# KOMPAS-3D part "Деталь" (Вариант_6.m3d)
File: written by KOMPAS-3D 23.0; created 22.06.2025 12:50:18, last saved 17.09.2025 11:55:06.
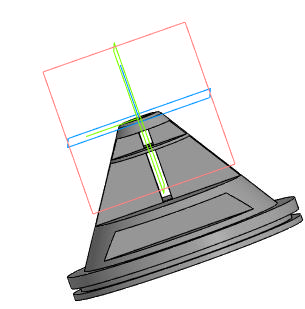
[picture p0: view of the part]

Document properties: Автор: admin; Организация: MGTU; Полное имя файла: C:\Users\ssafo\OneDrive\Desktop\ЦД_Грант\Решенные варианты\Вариант_6.m3d

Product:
- Part/product: Деталь
    Масса: 0.491475
    Форматы листов документа: A4

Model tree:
1. Эскиз:1
2. Элемент вращения:1
     Угол 1 = 360
3. Эскиз:2  (with: Элемент вращения:1)
4. Элемент выдавливания:1
     Расстояние 1 = 40; Расстояние 2 = 40
5. Эскиз:3  (with: Элемент вращения:1)
6. Элемент выдавливания:2
     Расстояние 1 = 40; Расстояние 2 = 40
7. Эскиз:4  (with: Элемент вращения:1)
8. Элемент выдавливания:3
     Расстояние 1 = 40; Расстояние 2 = 40
9. Зеркальный массив:1
10. Экземпляр ( 1 )
11. Экземпляр ( 2 )  (with: Элемент выдавливания:3, Элемент выдавливания:2, Элемент выдавливания:1)
12. Скругление:1  (with: Элемент вращения:1)
     Радиус = 2
13. Эскиз:5  (with: Элемент вращения:1)
14. Элемент выдавливания:4
15. Фаска:2  (with: Элемент выдавливания:4)
     Угол = 45; Длина 1 = 1; Длина 2 = 1
16. Эскиз:6  (with: Элемент вращения:1)
17. Элемент выдавливания:5
     Расстояние 2 = 6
